Omron CX-Programmer project NuevoProyecto (CX-Programmer 9.50)

# PLC NewPLC1: CP1L-E EM

## Program P1_4 (cyclic task 0)
Local symbols
B 100.00 BOOL
Etapa_0 10.00 BOOL
Etapa_1 10.01 BOOL
FSP 15.00 BOOL
p 0.00 BOOL

### Section Sección1_Programa_principal
; Programa principal (Etapas 0 y 1)

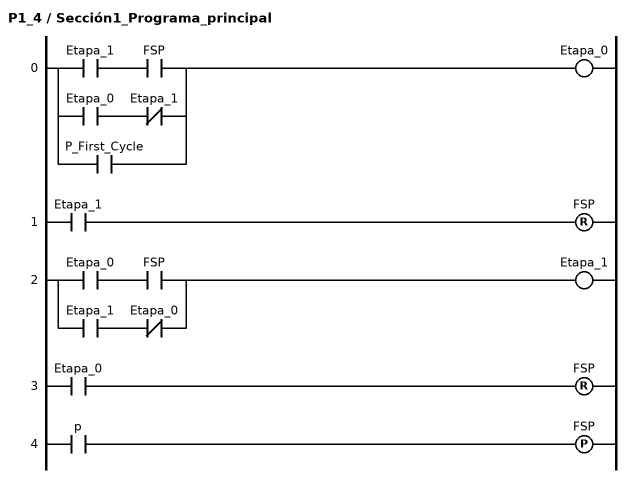
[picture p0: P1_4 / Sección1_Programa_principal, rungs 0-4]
; rung 0
LD Etapa_1
AND FSP
LD Etapa_0
ANDNOT Etapa_1
ORLD
OR P_First_Cycle
OUT Etapa_0
; rung 1
LD Etapa_1
RSET FSP
; rung 2
LD Etapa_0
AND FSP
LD Etapa_1
ANDNOT Etapa_0
ORLD
OUT Etapa_1
; rung 3
LD Etapa_0
RSET FSP
; rung 4
LD p
DIFU(013) FSP

### Section Sección2_Salida

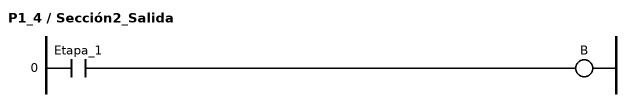
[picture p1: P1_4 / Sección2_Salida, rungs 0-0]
; rung 0
LD Etapa_1
OUT B

### Section Sección3_END
; rung 0
END(001)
